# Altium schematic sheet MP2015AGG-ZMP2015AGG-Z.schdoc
size 127 x 101 mm
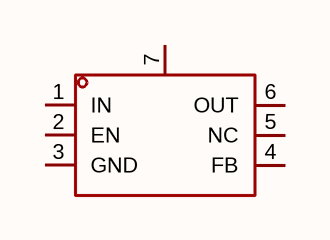
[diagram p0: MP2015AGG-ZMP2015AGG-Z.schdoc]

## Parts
U?  mp2015agg-z  [QFN-6_L2.0-W2.0-P0.65-BL-EP]  (value not drawn)

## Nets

Not connected (* = marked no-connect by the designer): U? 1(IN) 2(EN) 3(GND) 4(FB) 5(NC) 6(OUT) 7(PAD)

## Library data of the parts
U? = mp2015agg-z: 输出极性:正极;工作电压:24V;输出电压:1.215V~15V;输出电流:150mA;电源纹波抑制比(PSRR):55dB@(100kHz);输出类型:可调;; Manufacturer: MPS(芯源); AddInBom: yes; ModelId: fb954096014f4050b0970d73f1ef6cc4; ModelName: QFN-6_L2.0-W2.0-H0.8-P0.65; ModelTransform: 78.74,77.961,0,90,0,0,0,0,0; Output Configuration: 正极; Voltage - Supply: 24V; Output Current: 150mA; Voltage Dropout: 1.1V@(150mA); standby current: 3.3uA; Output Type: 可调; Number of Outputs: 1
